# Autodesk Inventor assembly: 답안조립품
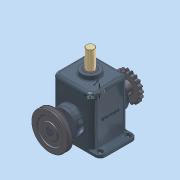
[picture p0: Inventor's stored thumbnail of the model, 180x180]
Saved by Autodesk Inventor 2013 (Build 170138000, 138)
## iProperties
Created: 2015-03
Part Number: 답안조립품
Document SubType Name: Assembly
Designer: Administrator
Author: Administrator
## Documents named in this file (15)
- C:\Documents and Settings\Administrator\바탕 화면\350305V1019\답안조립품.iam
- C:\Documents and Settings\Administrator\바탕 화면\350305V1019\본체.ipt
- C:\Documents and Settings\Administrator\바탕 화면\350305V1019\베어링 6205.ipt
- C:\Documents and Settings\Administrator\바탕 화면\350305V1019\커버.ipt
- C:\Documents and Settings\Administrator\바탕 화면\350305V1019\오일실.ipt
- C:\Documents and Settings\Administrator\바탕 화면\350305V1019\M4x0.5.ipt
- C:\Documents and Settings\Administrator\바탕 화면\350305V1019\편심축.ipt
- C:\Documents and Settings\Administrator\바탕 화면\350305V1019\체인 스프로킷.ipt
- C:\Documents and Settings\Administrator\바탕 화면\350305V1019\키 8x8.ipt
- C:\Documents and Settings\Administrator\바탕 화면\350305V1019\멈춤나사 M5x0.5.ipt
- C:\Documents and Settings\Administrator\바탕 화면\350305V1019\멈춤링.ipt
- C:\Documents and Settings\Administrator\바탕 화면\350305V1019\V-벨트풀리.ipt
- C:\Documents and Settings\Administrator\바탕 화면\350305V1019\부시.ipt
- C:\Documents and Settings\Administrator\바탕 화면\350305V1019\슬라이드.ipt
- C:\Documents and Settings\Administrator\바탕 화면\350305V1019\7-가변스프링.ipt
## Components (9 placed, 4 different names)
1. 5-체인 스프로킷:1 — 플러쉬:2, 각도:2
2. V-벨트풀리:1 — 플러쉬:4, 각도:4, 구속조건
3. 7-가변스프링:1
4. M4x0.5:1
5. M4x0.5:2
6. M4x0.5:3
7. M4x0.5:4
8. M4x0.5:5
9. M4x0.5:6
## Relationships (5: Angle 3, Flush 2)
- 플러쉬:2 [Flush]: 5-체인 스프로킷:1
- 각도:2 [Angle]: 5-체인 스프로킷:1
- 플러쉬:4 [Flush]: V-벨트풀리:1
- 각도:4 [Angle]: V-벨트풀리:1
- 구속조건 [Angle]: V-벨트풀리:1
